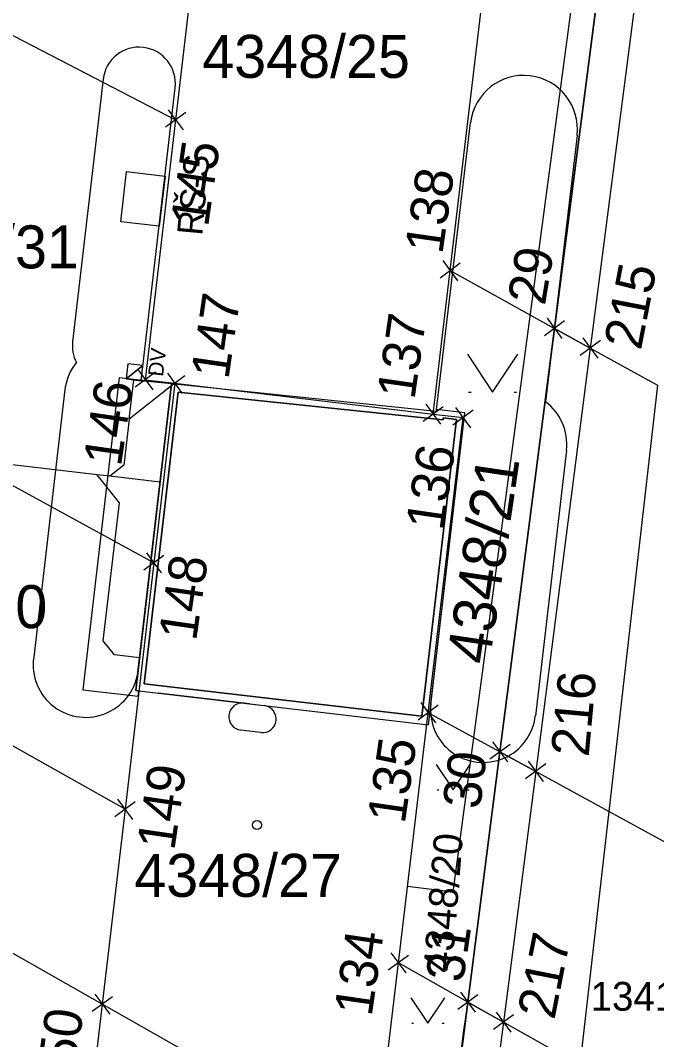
# Model space of a CAD drawing. Extents: x -735036 to -734743, y -1144813 to -1144181.
# Drawn here: x -734857.76 to -734832.59, y -1144568.07 to -1144527.79 of the extents above; entities that cross this region are included whole.
import ezdxf

# ---------------------------------------------------------------- set-up
doc = ezdxf.new("R2010")
doc.units = 0
for name, color, linetype in [('A3_Netisk', 7, 'Continuous'), ('A3_SIT_OBJEKTY_N01', 7, 'Continuous'), ('A3_SIT_PNB', 7, 'Continuous'), ('CKPLYN_POTRUBI_NT_PODZ_N', 7, 'Continuous'), ('CKTEXTY_MALE', 7, 'Continuous'), ('Groma (60)', 7, 'Continuous'), ('Katastr_HRANICE DRÁHY', 7, 'Continuous'), ('Katastr_Hranice parcel', 7, 'Continuous'), ('Katastr_Parcelní čísla', 7, 'Continuous'), ('Katastr_Slučkované čáry', 7, 'Continuous'), ('Katastr_Značky kultur', 7, 'Continuous'), ('SO01_CKKANALIZACE_JEDNOTNA_PODZ_N', 7, 'Continuous'), ('ZÁBORY_dočasné', 7, 'Continuous')]:
    doc.layers.add(name, color=color, linetype=linetype)

# ---------------------------------------------------------------- blocks, each defined once
blk = doc.blocks.new('POINT_DISPLAY')
for p, q in [((-0.35, -0.35), (0.35, 0.35)), ((-0.35, 0.35), (0.35, -0.35))]:
    blk.add_line(p, q)

msp = doc.modelspace()

# ---------------------------------------------------------------- linework, layer by layer
msp.add_line((-734853.579, -1144541.96), (-734852.914, -1144541.433))
for points in [[(-734853.579, -1144541.96), (-734852.983, -1144542.029), (-734852.914, -1144541.433), (-734853.51, -1144541.364)], [(-734853.579, -1144541.96), (-734852.983, -1144542.029), (-734852.914, -1144541.433)]]:
    msp.add_lwpolyline(points, close=True)
at = {"layer": 'A3_Netisk'}
for p, q in [((-734851.783, -1144542.154), (-734853.2, -1144554.266)), ((-734848.694, -1144554.798), (-734852.306, -1144554.375))]:
    msp.add_line(p, q, dxfattribs=at)
msp.add_lwpolyline([(-734852.04, -1144533.939), (-734852.27, -1144535.925), (-734853.791, -1144535.749), (-734853.561, -1144533.763)], close=True, dxfattribs=at)
at = {"layer": 'A3_SIT_OBJEKTY_N01'}
for p, q in [((-734853.848, -1144541.911), (-734855.291, -1144554.247)), ((-734851.783, -1144542.154), (-734853.848, -1144541.911)), ((-734851.783, -1144542.154), (-734853.2, -1144554.27)), ((-734853.2, -1144554.27), (-734851.783, -1144542.154)), ((-734841.306, -1144543.249), (-734851.783, -1144542.154)), ((-734852.868, -1144554.007), (-734851.519, -1144542.484)), ((-734851.519, -1144542.484), (-734841.043, -1144543.578)), ((-734841.297, -1144543.168), (-734841.306, -1144543.249)), ((-734840.177, -1144543.299), (-734841.297, -1144543.168)), ((-734840.51, -1144543.563), (-734841.883, -1144555.293)), ((-734841.619, -1144555.625), (-734840.177, -1144543.299)), ((-734841.043, -1144543.578), (-734841.034, -1144543.501)), ((-734841.034, -1144543.501), (-734840.51, -1144543.563)), ((-734841.883, -1144555.293), (-734852.868, -1144554.007)), ((-734855.291, -1144554.247), (-734853.107, -1144554.503)), ((-734853.2, -1144554.27), (-734841.619, -1144555.625)), ((-734853.081, -1144554.284), (-734853.2, -1144554.27)), ((-734853.107, -1144554.503), (-734853.081, -1144554.284))]:
    msp.add_line(p, q, dxfattribs=at)
msp.add_lwpolyline([(-734833.069, -1144512.138), (-734834.23, -1144521.36), (-734836.63, -1144539.96), (-734838.79, -1144556.7), (-734840.06, -1144566.59), (-734840.228, -1144567.714), (-734841.06, -1144574.32)], dxfattribs=at)
for points in [[(-734841.297, -1144543.168), (-734841.306, -1144543.249), (-734851.783, -1144542.154), (-734853.2, -1144554.27), (-734841.619, -1144555.625), (-734840.177, -1144543.299)], [(-734841.034, -1144543.501), (-734841.043, -1144543.578), (-734851.519, -1144542.484), (-734852.868, -1144554.007), (-734841.883, -1144555.293), (-734840.51, -1144543.563)]]:
    msp.add_lwpolyline(points, close=True, dxfattribs=at)
at = {"layer": 'A3_SIT_PNB'}
for points in [[(-734854.49, -1144530.117), (-734855.694, -1144540.487)], [(-734851.783, -1144542.154), (-734852.983, -1144542.029), (-734851.639, -1144530.45)], [(-734841.297, -1144543.168), (-734839.952, -1144531.834)], [(-734835.742, -1144532.333), (-734836.991, -1144542.861)], [(-734855.997, -1144542.375), (-734857.235, -1144552.957)], [(-734853.103, -1144553.441), (-734851.783, -1144542.154)], [(-734841.522, -1144554.796), (-734840.177, -1144543.299), (-734841.297, -1144543.168), (-734841.297, -1144543.168)], [(-734836.162, -1144544.775), (-734837.391, -1144555.279)], [(-734848.915, -1144554.772), (-734848.12, -1144554.865)], [(-734848.246, -1144555.937), (-734849.04, -1144555.844)]]:
    msp.add_lwpolyline(points, dxfattribs=at)
for centre, radius, start, end in [((-734853.064, -1144530.283), 1.435, 353.3334, 173.3271), ((-734837.847, -1144532.083), 2.12, 353.2364, 173.2364), ((-734854.268, -1144540.654), 1.435, 173.3281, 207.0342), ((-734853.931, -1144542.616), 2.08, 140.9633, 173.326), ((-734838.227, -1144544.534), 2.08, 353.326, 53.511), ((-734855.176, -1144553.254), 2.081, 171.7992, 354.8528), ((-734848.977, -1144555.308), 0.54, 83.3284, 263.326), ((-734848.977, -1144555.303), 0.535, 83.3235, 83.3283), ((-734848.183, -1144555.401), 0.54, 263.3293, 83.326), ((-734839.457, -1144555.038), 2.08, 173.326, 353.326)]:
    msp.add_arc(centre, radius, start, end, dxfattribs=at)
at = {"layer": 'CKPLYN_POTRUBI_NT_PODZ_N'}
msp.add_line((-734840.638, -1144562.238), (-734842.453, -1144562.022), dxfattribs=at)
msp.add_lwpolyline([(-734840.638, -1144562.238), (-734835.108, -1144520.855), (-734845.346, -1144519.67)], dxfattribs=at)
at = {"layer": 'Katastr_HRANICE DRÁHY'}
for points in [[(-734836.63, -1144539.96), (-734834.23, -1144521.36)], [(-734838.79, -1144556.7), (-734836.63, -1144539.96)], [(-734840.06, -1144566.59), (-734838.79, -1144556.7)], [(-734841.06, -1144574.32), (-734840.06, -1144566.59)]]:
    msp.add_lwpolyline(points, dxfattribs=at)
at = {"layer": 'Katastr_Hranice parcel'}
for points in [[(-734850.35, -1144520.8), (-734851.62, -1144531.72)], [(-734840.76, -1144537.68), (-734838.91, -1144522.14)], [(-734864.73, -1144524.92), (-734851.62, -1144531.72)], [(-734851.62, -1144531.72), (-734852.82, -1144541.99)], [(-734841.43, -1144543.35), (-734840.76, -1144537.68)], [(-734840.76, -1144537.68), (-734836.63, -1144539.96)], [(-734836.63, -1144539.96), (-734832.56, -1144542.21)], [(-734852.48, -1144549.23), (-734866.58, -1144541.54)], [(-734852.82, -1144541.99), (-734851.65, -1144542.13)], [(-734851.65, -1144542.13), (-734852.48, -1144549.23)], [(-734851.65, -1144542.13), (-734841.43, -1144543.35)], [(-734841.63, -1144555.15), (-734840.25, -1144543.49)], [(-734841.43, -1144543.35), (-734840.25, -1144543.49)], [(-734852.48, -1144549.23), (-734853.62, -1144558.97)], [(-734853.62, -1144558.97), (-734867.65, -1144551.09)], [(-734842.81, -1144565.04), (-734841.63, -1144555.15)], [(-734838.79, -1144556.7), (-734841.63, -1144555.15)], [(-734854.52, -1144566.67), (-734872.67, -1144556.37)], [(-734834.48, -1144559.05), (-734838.79, -1144556.7)], [(-734853.62, -1144558.97), (-734854.52, -1144566.67)], [(-734827.58, -1144562.82), (-734834.48, -1144559.05)], [(-734843.73, -1144572.8), (-734842.81, -1144565.04)], [(-734840.06, -1144566.59), (-734842.81, -1144565.04)], [(-734835.63, -1144569.08), (-734840.06, -1144566.59)], [(-734854.52, -1144566.67), (-734855.22, -1144572.62)], [(-734843.73, -1144572.8), (-734854.52, -1144566.67)]]:
    msp.add_lwpolyline(points, dxfattribs=at)
at = {"layer": 'Katastr_Slučkované čáry'}
for points in [[(-734832.56, -1144542.21), (-734834.48, -1144559.05)], [(-734834.48, -1144559.05), (-734835.63, -1144569.08)]]:
    msp.add_lwpolyline(points, dxfattribs=at)
at = {"layer": 'Katastr_Značky kultur'}
for p, q in [((-734840.03, -1144542.48), (-734839.93, -1144542.48)), ((-734838.23, -1144542.48), (-734838.13, -1144542.48)), ((-734841.31, -1144557.195), (-734840.64, -1144558.2)), ((-734840.64, -1144558.2), (-734839.97, -1144557.195)), ((-734841.277, -1144558.2), (-734841.21, -1144558.2)), ((-734840.071, -1144558.2), (-734840.003, -1144558.2)), ((-734842.31, -1144566.415), (-734841.64, -1144567.42)), ((-734841.64, -1144567.42), (-734840.97, -1144566.415)), ((-734842.277, -1144567.42), (-734842.21, -1144567.42)), ((-734841.071, -1144567.42), (-734841.003, -1144567.42))]:
    msp.add_line(p, q, dxfattribs=at)
msp.add_lwpolyline([(-734840.08, -1144540.98), (-734839.08, -1144542.48), (-734838.08, -1144540.98)], dxfattribs=at)
msp.add_circle((-734848.4, -1144559.59), 0.175, dxfattribs=at)
at = {"layer": 'SO01_CKKANALIZACE_JEDNOTNA_PODZ_N'}
msp.add_line((-734853.457, -1144543.555), (-734853.276, -1144541.995), dxfattribs=at)
for points in [[(-734851.904, -1144542.327), (-734853.457, -1144543.555), (-734853.669, -1144545.365), (-734854.223, -1144545.804)], [(-734852.237, -1144546.036), (-734854.223, -1144545.804), (-734854.72, -1144545.746), (-734865.823, -1144544.448), (-734866.393, -1144544.885)], [(-734853.049, -1144552.979), (-734854.043, -1144552.863), (-734854.481, -1144552.308), (-734853.843, -1144546.855), (-734854.72, -1144545.746)]]:
    msp.add_lwpolyline(points, dxfattribs=at)
at = {"layer": 'ZÁBORY_dočasné'}
for p, q in [((-734836.63, -1144539.96), (-734834.23, -1144521.36)), ((-734836.63, -1144539.96), (-734838.79, -1144556.7)), ((-734835.218, -1144540.74), (-734836.63, -1144539.96)), ((-734838.79, -1144556.7), (-734840.06, -1144566.59)), ((-734838.79, -1144556.7), (-734837.377, -1144557.471)), ((-734837.377, -1144557.471), (-734838.649, -1144567.383)), ((-734840.06, -1144566.59), (-734841.06, -1144574.32)), ((-734840.06, -1144566.59), (-734838.649, -1144567.383)), ((-734838.65, -1144567.383), (-734839.651, -1144575.118))]:
    msp.add_line(p, q, dxfattribs=at)
for points in [[(-734832.801, -1144522.006), (-734832.801, -1144522.006), (-734835.142, -1144540.152), (-734835.218, -1144540.74)], [(-734835.218, -1144540.74), (-734835.218, -1144540.74), (-734835.218, -1144540.74), (-734837.377, -1144557.471), (-734837.377, -1144557.471)]]:
    msp.add_lwpolyline(points, dxfattribs=at)

# ---------------------------------------------------------------- block references
at = {"layer": 'Groma (60)', "rotation": -98.65482414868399}
for p in [(-734851.62, -1144531.72), (-734840.76, -1144537.68), (-734836.63, -1144539.96), (-734835.218, -1144540.74), (-734852.82, -1144541.99), (-734851.65, -1144542.13), (-734841.43, -1144543.35), (-734840.25, -1144543.49), (-734852.48, -1144549.23), (-734841.63, -1144555.15), (-734838.79, -1144556.7), (-734837.377, -1144557.47), (-734853.62, -1144558.97), (-734842.81, -1144565.04), (-734840.06, -1144566.59), (-734854.52, -1144566.67), (-734838.65, -1144567.383)]:
    msp.add_blockref('POINT_DISPLAY', p, dxfattribs=at)

# ---------------------------------------------------------------- texts
at = {"layer": 'A3_Netisk'}
msp.add_text('RŠ-S', height=1, rotation=84.7414, dxfattribs=at).set_placement((-734850.57, -1144536.314))
at = {"layer": 'CKTEXTY_MALE'}
msp.add_text('DV', height=0.6, rotation=83.326, dxfattribs=at).set_placement((-734852.12, -1144541.888))
at = {"layer": 'Groma (60)'}
for s, rotation, p in [('145', 81.7835, (-734850.34, -1144535.984)), ('138', 81.7835, (-734841.071, -1144537.061)), ('29', 80.6425, (-734837.014, -1144539.088)), ('215', 79.0784, (-734833.215, -1144540.857)), ('147', 81.7835, (-734849.532, -1144542.009)), ('137', 81.7835, (-734842.175, -1144542.811)), ('146', 81.7835, (-734853.784, -1144545.454)), ('136', 81.7835, (-734841.032, -1144547.991)), ('148', 81.7835, (-734850.811, -1144552.349)), ('216', 84.7416, (-734835.284, -1144556.925)), ('135', 81.7835, (-734842.557, -1144559.576)), ('30', 83.024, (-734839.577, -1144558.997)), ('149', 81.7835, (-734851.672, -1144560.63)), ('31', 81.5353, (-734840.256, -1144565.852)), ('134', 81.7835, (-734843.868, -1144567.19)), ('217', 78.8523, (-734836.639, -1144567.318)), ('150', 81.7835, (-734855.736, -1144570.274))]:
    msp.add_text(s, height=1.5, rotation=rotation, dxfattribs=at).set_placement(p)
at = {"layer": 'Katastr_Parcelní čísla'}
for s, height, p in [('4348/25', 1.7, (-734850.567, -1144530.06)), ('1348/31', 1.7, (-734863.663, -1144537.59)), ('1348/30', 1.7, (-734864.914, -1144551.81)), ('4348/27', 1.7, (-734853.257, -1144562.43)), ('1341/55', 1.14, (-734835.206, -1144566.93))]:
    msp.add_text(s, height=height, dxfattribs=at).set_placement(p)
for s, height, rotation, p in [('4348/21', 1.7, 81.573, (-734839.215, -1144553.287)), ('4348/20', 1.14, 85.455, (-734840.688, -1144565.457))]:
    msp.add_text(s, height=height, rotation=rotation, dxfattribs=at).set_placement(p)

doc.saveas('drawing.dxf')
